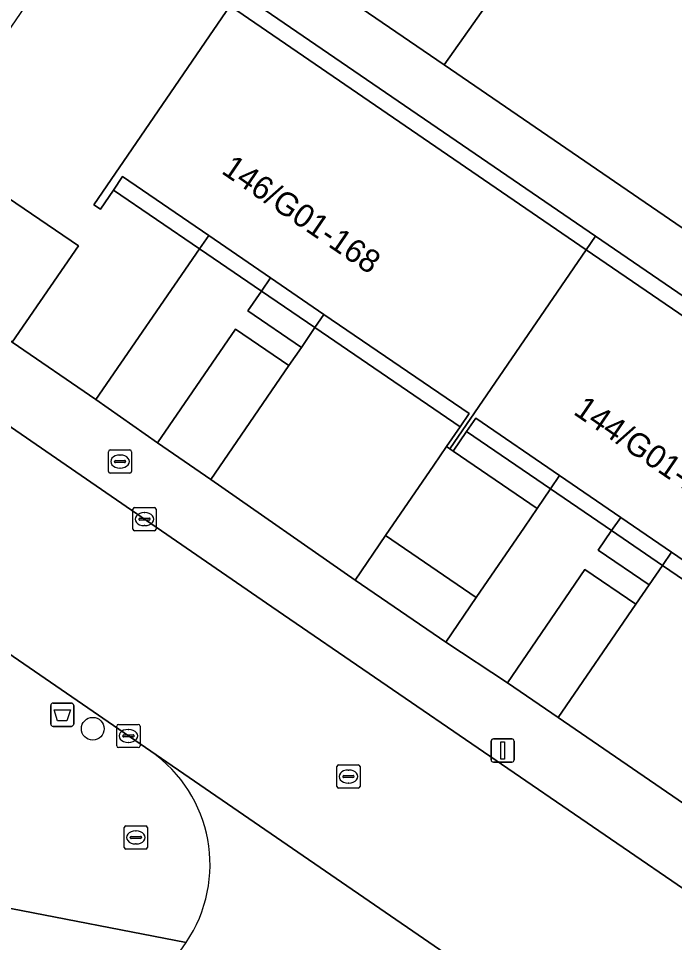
# Model space of a CAD drawing. Extents: x 160023 to 161302, y 384750 to 385707.
# Drawn here: x 160236.91 to 160265.17, y 385331.42 to 385371.24 of the extents above; entities that cross this region are included whole.
import ezdxf

# ---------------------------------------------------------------- set-up
doc = ezdxf.new("R2010")
doc.units = 0
for name, color, linetype in [('IMGEO_Afvalbak', 7, 'Continuous'), ('IMGEO_Boom', 7, 'Continuous'), ('IMGEO_Brandkraan', 7, 'Continuous'), ('IMGEO_Groenvoorziening', 7, 'Continuous'), ('IMGEO_Haag', 7, 'Continuous'), ('IMGEO_Kolk', 7, 'Continuous'), ('IMGEO_Lichtmast', 7, 'Continuous'), ('IMGEO_Pand', 7, 'Continuous'), ('IMGEO_Pand_nummerreeks', 7, 'Continuous'), ('IMGEO_Pand_overbouw', 7, 'Continuous'), ('IMGEO_Rijbaan_lokaal_gesloten', 7, 'Continuous'), ('IMGEO_Rijbaan_lokaal_open', 7, 'Continuous'), ('IMGEO_Rioolput', 7, 'Continuous'), ('IMGEO_Voetpad_open', 7, 'Continuous')]:
    doc.layers.add(name, color=color, linetype=linetype)

msp = doc.modelspace()

# ---------------------------------------------------------------- linework, layer by layer
at = {"layer": 'IMGEO_Afvalbak'}
for p, q in [((160238.3, 385340.834), (160238.3, 385341.634)), ((160238.3, 385341.634), (160238.3, 385340.834)), ((160238.4, 385341.734), (160239.19, 385341.734)), ((160239.19, 385341.734), (160238.4, 385341.734)), ((160239.29, 385341.634), (160239.29, 385340.834)), ((160239.29, 385340.834), (160239.29, 385341.634)), ((160239.19, 385340.734), (160238.4, 385340.734)), ((160238.4, 385340.734), (160239.19, 385340.734))]:
    msp.add_line(p, q, dxfattribs=at)
msp.add_lwpolyline([(160238.443, 385341.448), (160239.147, 385341.448), (160238.998, 385340.978), (160238.592, 385340.978), (160238.443, 385341.448)], dxfattribs=at)
for centre, start, end in [((160238.4, 385341.634), 90, 180), ((160238.4, 385341.634), 90, 180), ((160239.19, 385341.634), 0, 90), ((160239.19, 385341.634), 360, 90), ((160238.4, 385340.834), 180, 270), ((160238.4, 385340.834), 180, 270), ((160239.19, 385340.834), 270, 0), ((160239.19, 385340.834), 270, 0)]:
    msp.add_arc(centre, 0.1, start, end, dxfattribs=at)
at = {"layer": 'IMGEO_Boom'}
msp.add_circle((160240.111, 385340.632), 0.489, dxfattribs=at)
at = {"layer": 'IMGEO_Brandkraan'}
for p, q in [((160240.786, 385351.719), (160240.786, 385352.571)), ((160240.861, 385352.645), (160241.713, 385352.645)), ((160241.274, 385352.425), (160241.299, 385352.425)), ((160241.787, 385352.571), (160241.787, 385351.719)), ((160241.045, 385352.139), (160241.045, 385352.151)), ((160241.483, 385352.102), (160241.085, 385352.102)), ((160241.088, 385352.188), (160241.486, 385352.188)), ((160241.529, 385352.151), (160241.529, 385352.139)), ((160241.713, 385351.645), (160240.861, 385351.645)), ((160241.297, 385351.865), (160241.272, 385351.865)), ((160241.542, 385336.446), (160242.394, 385336.446)), ((160241.467, 385335.52), (160241.467, 385336.372)), ((160241.955, 385336.226), (160241.98, 385336.226)), ((160242.468, 385336.372), (160242.468, 385335.52)), ((160241.726, 385335.94), (160241.726, 385335.952)), ((160242.164, 385335.903), (160241.766, 385335.903)), ((160241.769, 385335.989), (160242.167, 385335.989)), ((160241.978, 385335.666), (160241.953, 385335.666)), ((160242.21, 385335.952), (160242.21, 385335.94)), ((160242.394, 385335.446), (160241.542, 385335.446))]:
    msp.add_line(p, q, dxfattribs=at)
for points in [[(160240.786, 385351.719), (160240.786, 385352.571)], [(160240.861, 385352.645), (160241.713, 385352.645)], [(160241.787, 385352.571), (160241.787, 385351.719)], [(160241.713, 385351.645), (160240.861, 385351.645)], [(160241.542, 385336.446), (160242.394, 385336.446)], [(160241.467, 385335.52), (160241.467, 385336.372)], [(160242.468, 385336.372), (160242.468, 385335.52)], [(160242.394, 385335.446), (160241.542, 385335.446)]]:
    msp.add_lwpolyline(points, dxfattribs=at)
for centre, radius, start, end in [((160240.863, 385352.569), 0.0765, 91.552, 178.448), ((160240.863, 385352.569), 0.0765, 91.552, 178.448), ((160241.711, 385352.569), 0.0765, 1.552, 88.448), ((160241.711, 385352.569), 0.0765, 1.552, 88.448), ((160241.085, 385352.148), 0.0403, 85.8775, 175.7526), ((160241.082, 385352.138), 0.0366, 178.938, 274.7102), ((160241.486, 385352.145), 0.043, 264.8664, 352.4533), ((160241.49, 385352.15), 0.0386, 1.7309, 96.639), ((160240.863, 385351.721), 0.0765, 181.552, 268.448), ((160240.863, 385351.721), 0.0765, 181.552, 268.448), ((160241.711, 385351.721), 0.0765, 271.552, 358.448), ((160241.711, 385351.721), 0.0765, 271.552, 358.448), ((160241.544, 385336.37), 0.0765, 91.552, 178.448), ((160241.544, 385336.37), 0.0765, 91.552, 178.448), ((160242.392, 385336.37), 0.0765, 1.552, 88.448), ((160242.392, 385336.37), 0.0765, 1.552, 88.448), ((160241.766, 385335.949), 0.0403, 85.8775, 175.7526), ((160241.763, 385335.939), 0.0366, 178.938, 274.7102), ((160242.167, 385335.946), 0.043, 264.8664, 352.4533), ((160242.171, 385335.951), 0.0386, 1.7309, 96.639), ((160241.544, 385335.522), 0.0765, 181.552, 268.448), ((160241.544, 385335.522), 0.0765, 181.552, 268.448), ((160242.392, 385335.522), 0.0765, 271.552, 358.448), ((160242.392, 385335.522), 0.0765, 271.552, 358.448)]:
    msp.add_arc(centre, radius, start, end, dxfattribs=at)
for centre, major_axis, ratio, start_param, end_param in [((160241.273, 385352.145), (-0.387, 0.002), 0.722429, 4.712389, 7.853982), ((160241.298, 385352.145), (-0.39, 0.002), 0.717154, 1.570796, 4.712389), ((160241.954, 385335.946), (-0.387, 0.002), 0.722429, 4.712389, 7.853982), ((160241.979, 385335.946), (-0.39, 0.002), 0.717154, 1.570796, 4.712389)]:
    msp.add_ellipse(centre, major_axis=major_axis, ratio=ratio, start_param=start_param, end_param=end_param, dxfattribs=at)
at = {"layer": 'IMGEO_Groenvoorziening'}
for points in [[(160315.68, 385363.866), (160306.615, 385370.103), (160313.003, 385379.066), (160289.333, 385396.646), (160287.972, 385399.436), (160280.314, 385415.136), (160263.246, 385389.432), (160260.904, 385385.906), (160264.985, 385383.044), (160264.09, 385381.775), (160255.248, 385369.236), (160298.852, 385339.366)], [(160255.248, 385369.236), (160264.09, 385381.775), (160250.21, 385391.03), (160241.671, 385378.537)], [(160240.25, 385354.826), (160244.709, 385361.312), (160241.003, 385363.844), (160240.439, 385363.021), (160240.159, 385363.212), (160246.425, 385372.368), (160246.682, 385372.799), (160240.679, 385376.854), (160233.099, 385365.798), (160239.495, 385361.44), (160236.64, 385357.286)], [(160236.64, 385357.286), (160239.495, 385361.44), (160233.099, 385365.798), (160230.249, 385361.642)], [(160244.709, 385361.312), (160245.105, 385361.888), (160241.4, 385364.424), (160241.003, 385363.844)], [(160249.68, 385357.916), (160250.072, 385358.489), (160247.768, 385360.066), (160247.374, 385359.491)], [(160246.794, 385358.642), (160249.099, 385357.067), (160249.68, 385357.916), (160247.374, 385359.491)], [(160246.255, 385357.856), (160242.9, 385352.954), (160245.205, 385351.377), (160248.56, 385356.279)], [(160258.706, 385349.322), (160259.255, 385350.125), (160255.637, 385352.597), (160255.494, 385352.695), (160255.351, 385352.793), (160254.804, 385351.993), (160252.726, 385348.958), (160256.628, 385346.287)], [(160264.649, 385347.67), (160265.04, 385348.241), (160262.851, 385349.739), (160262.46, 385349.167)], [(160262.46, 385349.167), (160261.885, 385348.327), (160264.075, 385346.831), (160264.649, 385347.67)], [(160252.726, 385348.958), (160251.411, 385347.036), (160255.313, 385344.365), (160256.628, 385346.287)], [(160261.313, 385347.491), (160257.974, 385342.613), (160260.164, 385341.115), (160263.502, 385345.993)]]:
    msp.add_lwpolyline(points, close=True, dxfattribs=at)
at = {"layer": 'IMGEO_Haag'}
for points in [[(160246.255, 385357.856), (160242.9, 385352.954), (160245.205, 385351.377), (160248.56, 385356.279)], [(160251.411, 385347.036), (160255.313, 385344.365), (160256.628, 385346.287), (160252.726, 385348.958)], [(160261.313, 385347.491), (160257.974, 385342.613), (160260.164, 385341.115), (160263.502, 385345.993)]]:
    msp.add_lwpolyline(points, close=True, dxfattribs=at)
at = {"layer": 'IMGEO_Kolk'}
for p, q in [((160241.839, 385349.237), (160241.839, 385350.089)), ((160241.914, 385350.163), (160242.766, 385350.163)), ((160242.84, 385350.089), (160242.84, 385349.237)), ((160242.098, 385349.657), (160242.098, 385349.669)), ((160242.536, 385349.62), (160242.138, 385349.62)), ((160242.141, 385349.706), (160242.539, 385349.706)), ((160242.327, 385349.943), (160242.352, 385349.943)), ((160242.582, 385349.669), (160242.582, 385349.657)), ((160242.766, 385349.163), (160241.914, 385349.163)), ((160242.35, 385349.383), (160242.325, 385349.383)), ((160241.221, 385340.82), (160242.073, 385340.82)), ((160241.146, 385339.894), (160241.146, 385340.746)), ((160241.634, 385340.6), (160241.659, 385340.6)), ((160242.147, 385340.746), (160242.147, 385339.894)), ((160241.405, 385340.314), (160241.405, 385340.326)), ((160241.843, 385340.277), (160241.445, 385340.277)), ((160241.448, 385340.363), (160241.846, 385340.363)), ((160241.657, 385340.04), (160241.632, 385340.04)), ((160241.889, 385340.326), (160241.889, 385340.314)), ((160242.073, 385339.82), (160241.221, 385339.82))]:
    msp.add_line(p, q, dxfattribs=at)
for points in [[(160241.839, 385349.237), (160241.839, 385350.089)], [(160241.914, 385350.163), (160242.766, 385350.163)], [(160242.84, 385350.089), (160242.84, 385349.237)], [(160242.766, 385349.163), (160241.914, 385349.163)], [(160241.221, 385340.82), (160242.073, 385340.82)], [(160241.146, 385339.894), (160241.146, 385340.746)], [(160242.147, 385340.746), (160242.147, 385339.894)], [(160242.073, 385339.82), (160241.221, 385339.82)]]:
    msp.add_lwpolyline(points, dxfattribs=at)
for centre, radius, start, end in [((160241.916, 385350.087), 0.0765, 91.552, 178.448), ((160241.916, 385350.087), 0.0765, 91.552, 178.448), ((160242.764, 385350.087), 0.0765, 1.552, 88.448), ((160242.764, 385350.087), 0.0765, 1.552, 88.448), ((160242.138, 385349.666), 0.0403, 85.8775, 175.7526), ((160242.135, 385349.656), 0.0366, 178.938, 274.7102), ((160242.539, 385349.663), 0.043, 264.8664, 352.4533), ((160242.543, 385349.668), 0.0386, 1.7309, 96.639), ((160241.916, 385349.239), 0.0765, 181.552, 268.448), ((160241.916, 385349.239), 0.0765, 181.552, 268.448), ((160242.764, 385349.239), 0.0765, 271.552, 358.448), ((160242.764, 385349.239), 0.0765, 271.552, 358.448), ((160241.223, 385340.744), 0.0765, 91.552, 178.448), ((160241.223, 385340.744), 0.0765, 91.552, 178.448), ((160242.071, 385340.744), 0.0765, 1.552, 88.448), ((160242.071, 385340.744), 0.0765, 1.552, 88.448), ((160241.445, 385340.323), 0.0403, 85.8775, 175.7526), ((160241.442, 385340.313), 0.0366, 178.938, 274.7102), ((160241.846, 385340.32), 0.043, 264.8664, 352.4533), ((160241.85, 385340.325), 0.0386, 1.7309, 96.639), ((160241.223, 385339.896), 0.0765, 181.552, 268.448), ((160241.223, 385339.896), 0.0765, 181.552, 268.448), ((160242.071, 385339.896), 0.0765, 271.552, 358.448), ((160242.071, 385339.896), 0.0765, 271.552, 358.448)]:
    msp.add_arc(centre, radius, start, end, dxfattribs=at)
for centre, major_axis, ratio, start_param, end_param in [((160242.326, 385349.663), (-0.387, 0.002), 0.722429, 4.712389, 7.853982), ((160242.351, 385349.663), (-0.39, 0.002), 0.717154, 1.570796, 4.712389), ((160241.633, 385340.32), (-0.387, 0.002), 0.722429, 4.712389, 7.853982), ((160241.658, 385340.32), (-0.39, 0.002), 0.717154, 1.570796, 4.712389)]:
    msp.add_ellipse(centre, major_axis=major_axis, ratio=ratio, start_param=start_param, end_param=end_param, dxfattribs=at)
at = {"layer": 'IMGEO_Lichtmast'}
for p, q in [((160257.271, 385339.291), (160257.271, 385340.091)), ((160257.271, 385340.091), (160257.271, 385339.291)), ((160257.371, 385340.191), (160258.161, 385340.191)), ((160258.161, 385340.191), (160257.371, 385340.191)), ((160258.261, 385340.091), (160258.261, 385339.291)), ((160258.261, 385339.291), (160258.261, 385340.091)), ((160258.161, 385339.191), (160257.371, 385339.191)), ((160257.371, 385339.191), (160258.161, 385339.191))]:
    msp.add_line(p, q, dxfattribs=at)
msp.add_lwpolyline([(160257.691, 385340.066), (160257.841, 385340.066), (160257.841, 385339.316), (160257.691, 385339.316), (160257.691, 385340.066)], dxfattribs=at)
for centre, start, end in [((160257.371, 385340.091), 90, 180), ((160257.371, 385340.091), 90, 180), ((160258.161, 385340.091), 0, 90), ((160258.161, 385340.091), 360, 90), ((160257.371, 385339.291), 180, 270), ((160257.371, 385339.291), 180, 270), ((160258.161, 385339.291), 270, 0), ((160258.161, 385339.291), 270, 0)]:
    msp.add_arc(centre, 0.1, start, end, dxfattribs=at)
at = {"layer": 'IMGEO_Pand'}
for points in [[(160246.313, 385371.579), (160246.717, 385372.168), (160246.425, 385372.368), (160240.159, 385363.212), (160240.439, 385363.021), (160241.003, 385363.844), (160241.4, 385364.424), (160245.105, 385361.888), (160247.768, 385360.066), (160250.072, 385358.489), (160256.322, 385354.212), (160255.933, 385353.643), (160255.351, 385352.793), (160255.494, 385352.695), (160261.37, 385361.274)], [(160261.37, 385361.274), (160255.494, 385352.695), (160255.637, 385352.597), (160256.212, 385353.437), (160256.606, 385354.013), (160260.222, 385351.538), (160262.851, 385349.739), (160265.04, 385348.241), (160271.44, 385343.861), (160271.052, 385343.294), (160270.481, 385342.459), (160270.597, 385342.379), (160276.464, 385350.944)]]:
    msp.add_lwpolyline(points, close=True, dxfattribs=at)
at = {"layer": 'IMGEO_Pand_overbouw'}
for points in [[(160246.717, 385372.168), (160246.313, 385371.579), (160261.37, 385361.274), (160261.77, 385361.859)], [(160241.003, 385363.844), (160244.709, 385361.312), (160247.374, 385359.491), (160249.68, 385357.916), (160255.933, 385353.643), (160256.322, 385354.212), (160250.072, 385358.489), (160247.768, 385360.066), (160245.105, 385361.888), (160241.4, 385364.424)], [(160276.464, 385350.944), (160276.861, 385351.524), (160261.77, 385361.859), (160261.37, 385361.274)], [(160256.212, 385353.437), (160259.83, 385350.964), (160262.46, 385349.167), (160264.649, 385347.67), (160271.052, 385343.294), (160271.44, 385343.861), (160265.04, 385348.241), (160262.851, 385349.739), (160260.222, 385351.538), (160256.606, 385354.013)]]:
    msp.add_lwpolyline(points, close=True, dxfattribs=at)
at = {"layer": 'IMGEO_Rijbaan_lokaal_gesloten'}
msp.add_lwpolyline([(160293.953, 385312.653), (160293.613, 385314.078), (160293.191, 385314.733), (160292.372, 385315.253), (160271.303, 385329.79), (160247.822, 385345.89), (160229.443, 385358.537), (160224.858, 385351.874), (160242.607, 385339.66), (160256.475, 385330.138), (160273.166, 385318.717), (160288.128, 385308.422), (160293.07, 385305.05), (160301.992, 385298.533), (160308.557, 385293.653), (160313.407, 385300.179), (160311.165, 385301.848), (160300.495, 385309.611)], dxfattribs=at)
at = {"layer": 'IMGEO_Rijbaan_lokaal_open'}
for points in [[(160250.072, 385358.489), (160249.68, 385357.916), (160255.933, 385353.643), (160256.322, 385354.212)], [(160255.933, 385353.643), (160249.68, 385357.916), (160249.099, 385357.067), (160248.56, 385356.279), (160245.205, 385351.377), (160251.411, 385347.036), (160252.726, 385348.958), (160254.804, 385351.993), (160255.351, 385352.793)], [(160265.04, 385348.241), (160264.649, 385347.67), (160271.052, 385343.294), (160271.44, 385343.861)], [(160271.052, 385343.294), (160264.649, 385347.67), (160264.075, 385346.831), (160263.502, 385345.993), (160260.164, 385341.115), (160266.559, 385336.718), (160269.848, 385341.524), (160270.481, 385342.459)]]:
    msp.add_lwpolyline(points, close=True, dxfattribs=at)
msp.add_lwpolyline([(160256.475, 385330.138), (160242.607, 385339.66)], dxfattribs=at)
msp.add_arc((160239.211, 385334.771), 5.953, 325.7202, 55.2184, dxfattribs=at)
at = {"layer": 'IMGEO_Rioolput'}
for p, q in [((160250.624, 385338.146), (160250.624, 385338.998)), ((160250.699, 385339.072), (160251.551, 385339.072)), ((160251.112, 385338.852), (160251.137, 385338.852)), ((160251.625, 385338.998), (160251.625, 385338.146)), ((160250.883, 385338.566), (160250.883, 385338.578)), ((160251.321, 385338.529), (160250.923, 385338.529)), ((160250.926, 385338.615), (160251.324, 385338.615)), ((160251.367, 385338.578), (160251.367, 385338.566)), ((160251.551, 385338.072), (160250.699, 385338.072)), ((160251.135, 385338.292), (160251.11, 385338.292))]:
    msp.add_line(p, q, dxfattribs=at)
for points in [[(160250.624, 385338.146), (160250.624, 385338.998)], [(160250.699, 385339.072), (160251.551, 385339.072)], [(160251.625, 385338.998), (160251.625, 385338.146)], [(160251.551, 385338.072), (160250.699, 385338.072)]]:
    msp.add_lwpolyline(points, dxfattribs=at)
for centre, radius, start, end in [((160250.701, 385338.996), 0.0765, 91.552, 178.448), ((160250.701, 385338.996), 0.0765, 91.552, 178.448), ((160251.549, 385338.996), 0.0765, 1.552, 88.448), ((160251.549, 385338.996), 0.0765, 1.552, 88.448), ((160250.923, 385338.575), 0.0403, 85.8775, 175.7526), ((160250.92, 385338.565), 0.0366, 178.938, 274.7102), ((160251.324, 385338.572), 0.043, 264.8664, 352.4533), ((160251.328, 385338.577), 0.0386, 1.7309, 96.639), ((160250.701, 385338.148), 0.0765, 181.552, 268.448), ((160250.701, 385338.148), 0.0765, 181.552, 268.448), ((160251.549, 385338.148), 0.0765, 271.552, 358.448), ((160251.549, 385338.148), 0.0765, 271.552, 358.448)]:
    msp.add_arc(centre, radius, start, end, dxfattribs=at)
for centre, major_axis, ratio, start_param, end_param in [((160251.111, 385338.572), (-0.387, 0.002), 0.722429, 4.712389, 7.853982), ((160251.136, 385338.572), (-0.39, 0.002), 0.717154, 1.570796, 4.712389)]:
    msp.add_ellipse(centre, major_axis=major_axis, ratio=ratio, start_param=start_param, end_param=end_param, dxfattribs=at)
at = {"layer": 'IMGEO_Voetpad_open'}
for points in [[(160198.6, 385379.612), (160208.723, 385372.739), (160212.266, 385370.246), (160223.749, 385362.456), (160226.581, 385360.507), (160229.443, 385358.537), (160247.822, 385345.89), (160271.303, 385329.79), (160292.372, 385315.253), (160293.191, 385314.733), (160293.613, 385314.078), (160293.953, 385312.653)], [(160298.852, 385339.366), (160255.248, 385369.236), (160241.671, 385378.537)], [(160303.049, 385310.426), (160300.756, 385313.228), (160288.926, 385321.336), (160287.112, 385322.608), (160281.811, 385326.234), (160275.339, 385330.729), (160273.082, 385332.274), (160270.361, 385334.116), (160266.559, 385336.718), (160260.164, 385341.115), (160257.974, 385342.613), (160255.313, 385344.365), (160251.411, 385347.036), (160245.205, 385351.377), (160242.9, 385352.954), (160240.25, 385354.826), (160236.64, 385357.286), (160230.249, 385361.642), (160228.545, 385362.775), (160218.323, 385369.74), (160213.523, 385372.603)], [(160246.717, 385372.168), (160261.77, 385361.859), (160276.861, 385351.524), (160291.919, 385341.211), (160292.173, 385341.037), (160290.042, 385337.923), (160291.635, 385336.821), (160293.982, 385340.246)], [(160195.832, 385365.824), (160226.2, 385344.936), (160225.751, 385344.213), (160231.464, 385340.296), (160229.174, 385336.956), (160231.657, 385335.254), (160232.028, 385335.796), (160236.144, 385332.974), (160244.13, 385331.418)], [(160242.607, 385339.66), (160224.858, 385351.874)], [(160241.887, 385328.157), (160244.13, 385331.418), (160236.144, 385332.974), (160232.498, 385327.657), (160231.862, 385328.093), (160230.884, 385326.666), (160231.079, 385326.532), (160233.506, 385324.768), (160222.754, 385309.07), (160221.619, 385307.412), (160196.571, 385270.843), (160195.714, 385269.592), (160194.296, 385267.521), (160186.568, 385258.673), (160181.176, 385252.527), (160180.818, 385252.107)]]:
    msp.add_lwpolyline(points, dxfattribs=at)
for points in [[(160261.37, 385361.274), (160261.77, 385361.859), (160246.717, 385372.168), (160246.313, 385371.579)], [(160247.374, 385359.491), (160247.768, 385360.066), (160245.105, 385361.888), (160244.709, 385361.312)], [(160276.464, 385350.944), (160276.861, 385351.524), (160261.77, 385361.859), (160261.37, 385361.274)], [(160248.56, 385356.279), (160249.099, 385357.067), (160246.794, 385358.642), (160247.374, 385359.491), (160244.709, 385361.312), (160240.25, 385354.826), (160242.9, 385352.954), (160246.255, 385357.856)], [(160256.606, 385354.013), (160256.212, 385353.437), (160259.83, 385350.964), (160260.222, 385351.538)], [(160256.212, 385353.437), (160255.637, 385352.597), (160259.255, 385350.125), (160259.83, 385350.964)], [(160262.46, 385349.167), (160262.851, 385349.739), (160260.222, 385351.538), (160259.83, 385350.964)], [(160261.313, 385347.491), (160263.502, 385345.993), (160264.075, 385346.831), (160261.885, 385348.327), (160262.46, 385349.167), (160259.83, 385350.964), (160259.255, 385350.125), (160258.706, 385349.322), (160256.628, 385346.287), (160255.313, 385344.365), (160257.974, 385342.613)]]:
    msp.add_lwpolyline(points, close=True, dxfattribs=at)
msp.add_arc((160239.211, 385334.771), 5.953, 325.7202, 55.2184, dxfattribs=at)

# ---------------------------------------------------------------- texts
at = {"layer": 'IMGEO_Pand_nummerreeks'}
for s, rotation, p in [('146/G01-168', 325.6139, (160245.61, 385364.596)), ('144/G01-156', 325.6133, (160260.77, 385354.217))]:
    msp.add_text(s, height=1, rotation=rotation, dxfattribs=at).set_placement(p)

doc.saveas('drawing.dxf')
